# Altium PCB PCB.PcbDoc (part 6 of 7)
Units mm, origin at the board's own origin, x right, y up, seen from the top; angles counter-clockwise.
Board outline 243.2 x 142.8 mm, 4 copper layers (Top Layer, Layer 1, Layer 2, Bottom Layer), stack 0.603 mm thick; 451 components, 380 nets, 2276 pads, 1520 vias.
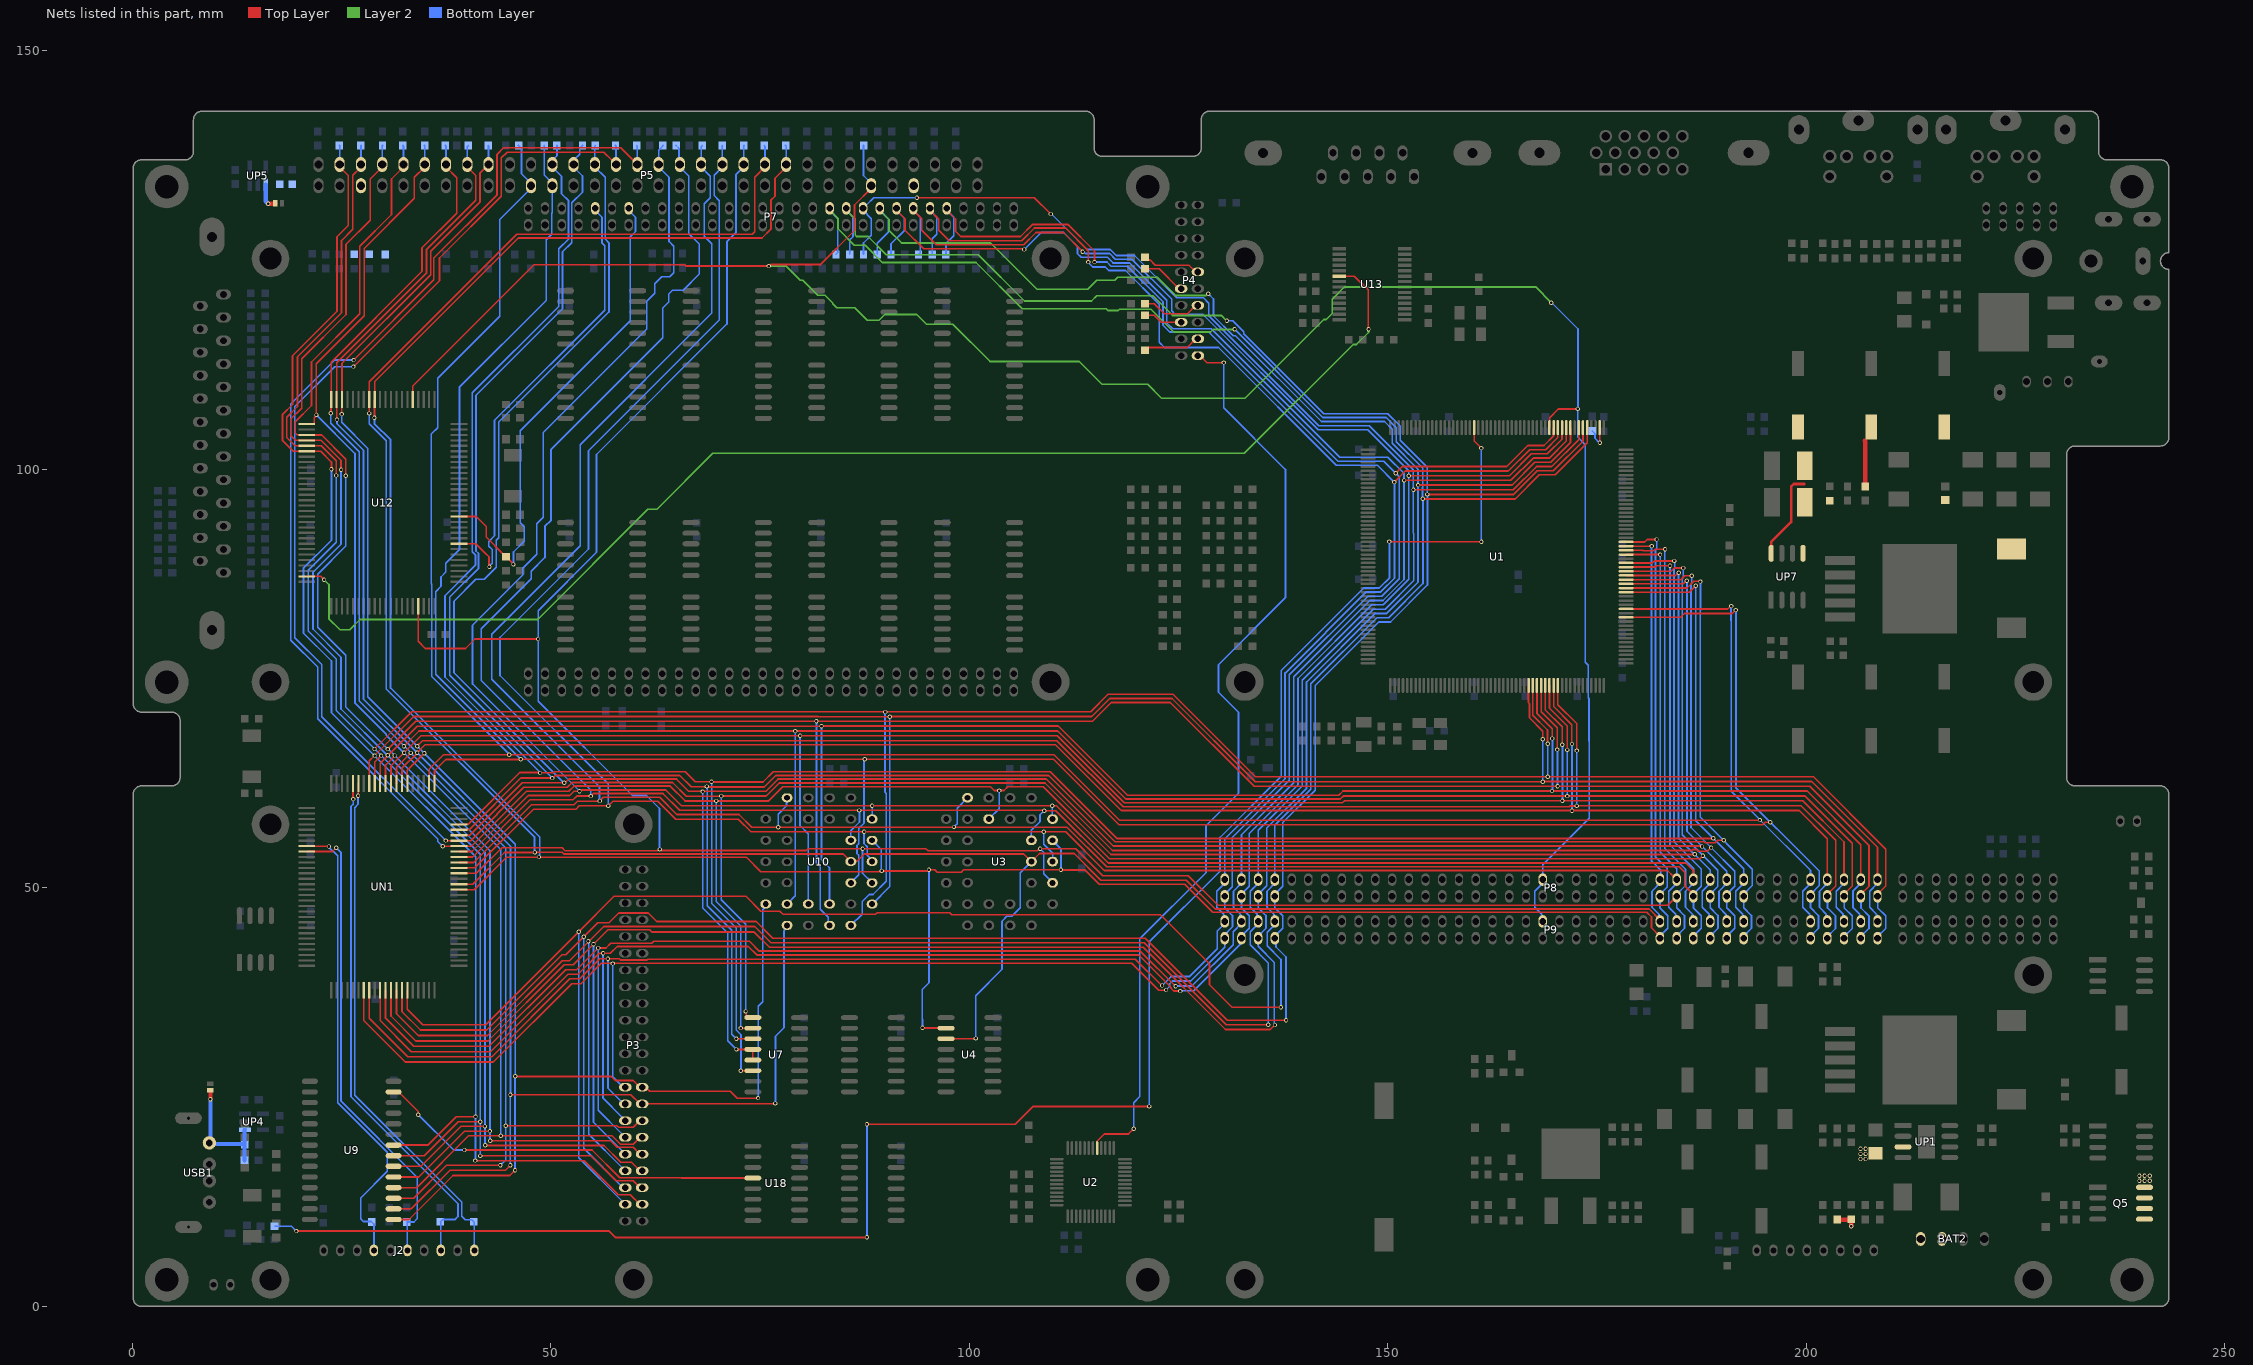
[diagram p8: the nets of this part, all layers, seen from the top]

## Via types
v1: diameter 0.508, hole 0.305, Top Layer to Bottom Layer, tented both sides, 1451 vias
v2: diameter 0.508, hole 0.3, Top Layer to Bottom Layer, 67 vias
v3: diameter 1.2, hole 1.2, Top Layer to Bottom Layer, 2 vias

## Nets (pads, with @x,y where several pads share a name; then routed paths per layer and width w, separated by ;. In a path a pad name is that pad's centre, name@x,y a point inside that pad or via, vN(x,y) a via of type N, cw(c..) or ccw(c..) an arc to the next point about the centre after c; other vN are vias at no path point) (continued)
SA8: P5.46 P8.28 P9.28 R71.1 U1.186 U3.27 U4.2 U10.27 U12.42 UN1.15 | length 364.3
  Top Layer w0.203: v1(28.916,106.188) 28.933,106.205 28.933,108.337 U12.42@28.951,108.354 28.951,110.506 46.095,127.651 75.221,127.651 76.287,128.717 76.287,132.146 76.77,132.629 76.77,134.8 78.11,136.14 P5.46@78.11,136.44 ; UN1.15@39.026,49.8 40.829,49.8 44.69,53.66 48.537,53.66 v1(48.576,53.7) ; v1@48.627,53.66 73.366,53.66 75.094,51.933 89.165,51.933 89.209,51.976 89.378,51.976 89.394,51.993 89.394,52.035 94.95,52.035 95.103,52.187 v1@95.185,52.187 ; v1(94.398,33.299) 94.422,33.275 97.187,33.275 U4.2@97.212,33.25 ; v1@95.236,52.187 95.865,52.187 96.157,51.895 99.008,51.895 99.3,52.187 v1(110.933,52.187) ; v1@110.933,52.136 113.827,52.136 115.511,50.452 125.724,50.452 129.094,47.082 180.935,47.082 181.494,46.523 181.494,45.256 182.5,44.25 P9.28@182.5,44 ; U1.186@178.463,91.336 180.692,91.336 180.99,91.633 v1(182.104,91.633)
  Bottom Layer w0.203: v1(28.916,106.188) 28.916,105.476 30.847,103.546 30.847,73.894 48.652,56.089 48.652,54.013 48.634,53.995 48.634,53.758 v1(48.576,53.7) ; R71.1@78.04,138.7 78.11,138.63 P5.46@78.11,136.44 ; U10.27@88.378,55.692 89.47,54.6 89.47,52.083 v1(89.518,52.035) ; v1(94.398,33.299) 94.398,34.287 94.372,34.313 94.372,37.862 95.17,38.659 95.17,52.177 v1(95.16,52.187) ; U3.27@109.942,55.692 110.933,54.702 v1(110.933,52.187) ; v1(182.104,91.633) 182.104,90.544 181.962,90.402 181.962,53.726 183.364,52.324 183.364,50.114 182.5,49.25 P8.28@182.5,49 182.5,47.638 183.437,46.701 183.437,45.187 182.5,44.25 P9.28@182.5,44
SA9: P5.44 P8.27 P9.27 R72.1 U1.185 U3.26 U4.3 U10.26 U12.43 UN1.16 | length 355.3
  Top Layer w0.203: v1(28.307,106.696) 28.304,106.699 28.304,108.351 U12.43@28.301,108.354 28.301,110.494 45.915,128.108 74.052,128.108 74.357,128.413 74.357,134.927 75.57,136.14 P5.44@75.57,136.44 ; UN1.16@39.026,50.45 40.667,50.45 44.461,54.245 v1(48.093,54.245) ; v1@48.093,54.259 51.344,54.259 51.551,54.051 84.939,54.051 U10.26@85.838,53.152 85.936,53.251 86.635,53.251 87.439,54.054 106.501,54.054 U3.26@107.402,53.152 108.368,54.118 112.532,54.118 115.712,50.937 125.924,50.937 129.373,47.488 181.215,47.488 182.5,46.203 P9.27@182.5,46 ; U4.3@97.212,31.98 97.232,32 100.728,32 v1(100.748,32.02) ; U1.185@178.463,90.836 178.468,90.841 181.514,90.841 v1(181.52,90.846)
  Bottom Layer w0.203: v1(28.307,106.696) 28.307,105.451 30.313,103.444 30.313,73.777 48.051,56.039 48.051,54.287 v1(48.093,54.245) ; R72.1@75.5,138.7 75.57,138.63 P5.44@75.57,136.44 ; v1(100.748,32.02) 100.748,37.125 103.897,40.275 103.897,46.04 104.481,46.625 105.066,46.625 106.082,47.641 106.082,51.832 U3.26@107.402,53.152 ; v1@181.491,90.897 181.491,90.846 181.491,53.232 182.612,52.111 182.612,51.112 P8.27@182.5,51 ; P9.27@182.384,46.116 182.384,46.865 181.558,47.691 181.558,49.622 P8.27@182.5,50.564
SA10: P5.42 P8.26 P9.26 R73.1 U1.184 U3.23 U10.23 U12.97 UN1.18 | length 333.7
  Top Layer w0.203: U12.97@34.151,83.654 34.151,79.46 34.997,78.614 39.798,78.614 40.931,79.746 v1(48.474,79.746) ; UN1.18@39.026,51.75 41.103,51.75 44.156,54.803 51.338,54.803 51.684,54.458 62.757,54.458 62.91,54.61 63.074,54.61 63.211,54.473 80.514,54.473 80.738,54.697 87.228,54.697 v1@87.23,54.7 ; v1(87.232,54.697) 94.803,54.697 95.065,54.435 108.12,54.435 108.361,54.676 v1(108.444,54.676) 108.469,54.702 112.71,54.702 115.935,51.476 126.148,51.476 129.704,47.92 183.42,47.92 184.098,48.598 184.132,48.598 184.5,48.966 P8.26@184.5,49 ; U1.184@178.463,90.336 180.48,90.336 180.528,90.287 181.751,90.287 181.929,90.465 v1(183.12,90.465)
  Bottom Layer w0.203: v1(62.992,54.61) 62.978,54.624 62.978,59.502 61.428,61.052 59.752,61.052 48.486,72.318 48.486,79.735 v1(48.474,79.746) 48.474,83.132 55.44,90.098 55.44,101.783 71.029,117.372 71.029,127.219 72.105,128.294 72.105,135.215 73.03,136.14 P5.42@73.03,136.44 73.03,138.668 R73.1@73.062,138.7 ; v1(87.232,54.697) 87.232,51.758 U10.23@88.378,50.612 ; v1(108.444,54.676) 108.876,54.245 108.876,51.679 U3.23@109.942,50.612 ; v1(183.12,90.465) 183.079,90.424 183.079,54.717 185.549,52.248 185.549,50.299 184.5,49.25 P8.26@184.5,49 184.5,47.638 185.437,46.701 185.437,45.187 P9.26@184.5,44.25
SA11: P5.40 P8.25 P9.25 R74.1 U1.183 U3.25 U10.25 UN1.19 | length 305.3
  Top Layer w0.203: UN1.19@39.026,52.4 40.915,52.4 47.916,59.401 52.996,59.401 53.404,59.809 56.854,59.809 v1(56.856,59.807) 57.415,60.366 62.748,60.366 64.897,58.217 72.391,58.217 73.9,56.708 v1(87.413,56.708) v1(108.876,56.708) 111.498,56.708 116.121,52.086 183.414,52.086 184.098,51.402 184.132,51.402 184.5,51.034 P8.25@184.5,51 ; U1.183@178.463,89.836 178.466,89.833 182.518,89.833 v1(182.52,89.83)
  Bottom Layer w0.203: v1(56.856,59.807) 56.856,62.449 43.928,75.377 43.928,79.923 54.494,90.49 54.494,102.222 70.128,117.856 70.128,132.108 69.506,132.731 69.506,135.156 70.49,136.14 P5.40@70.49,136.44 70.49,138.68 R74.1@70.471,138.7 ; v1(87.413,56.708) 87.413,55.307 87.791,54.929 87.791,53.916 88.378,53.329 U10.25@88.378,53.152 ; v1(108.876,56.708) 108.876,55.21 109.942,54.143 U3.25@109.942,53.152 ; v1(182.52,89.83) 182.55,89.801 182.55,54.256 184.5,52.306 P8.25@184.5,51 ; P9.25@184.384,46.116 184.384,46.865 183.558,47.691 183.558,49.622 P8.25@184.5,50.564
SA12: P5.38 P8.24 P9.24 R75.1 U1.181 U3.4 U10.4 UN1.20 | length 313.9
  Top Layer w0.203: UN1.20@39.026,53.05 40.777,53.05 47.685,59.958 52.765,59.958 53.173,60.366 55.815,60.366 v1(55.84,60.391) 56.272,60.823 63.002,60.823 65.043,58.782 72.473,58.782 73.988,57.267 v1(77.151,57.267) 98.157,57.267 111.668,57.267 116.401,52.534 184.805,52.534 185.482,51.857 185.482,50.268 186.5,49.25 P8.24@186.5,49 ; U1.181@178.463,88.836 181.577,88.836 181.81,89.068 v1(184.212,89.068)
  Bottom Layer w0.203: v1@55.8,60.391 55.8,62.083 42.94,74.943 42.94,80.333 53.506,90.899 53.506,102.964 69.226,118.684 69.226,126.965 68.337,127.854 68.337,131.74 69.048,132.451 69.048,135.042 67.95,136.14 P5.38@67.95,136.44 67.95,138.566 R75.1@68.083,138.7 ; v1(77.151,57.267) 77.151,58.817 78.152,59.818 78.152,60.707 U10.4@78.218,60.772 ; v1(98.157,57.293) 98.538,57.674 98.538,59.528 U3.4@99.782,60.772 ; v1(184.212,89.068) 184.263,89.017 184.263,88.209 184.187,88.133 184.187,55.515 187.438,52.263 187.438,50.188 186.5,49.25 P8.24@186.5,49 186.5,47.638 187.437,46.701 187.437,45.187 186.5,44.25 P9.24@186.5,44
SA13: P5.36 P8.23 P9.23 R76.1 U1.180 U3.28 U10.28 UN1.21 | length 308.7
  Top Layer w0.203: UN1.21@39.026,53.7 40.665,53.7 47.509,60.544 52.64,60.544 53.072,60.976 v1@54.775,60.976 ; v1(54.775,60.977) 55.078,61.28 63.383,61.28 65.389,59.274 86.839,59.274 v1(86.854,59.259) ; v1@86.854,59.274 108.9,59.274 v1(108.941,59.233) 110.338,59.233 116.587,52.983 185.601,52.983 186.5,52.084 P8.23@186.5,51 ; U1.180@178.463,88.336 181.875,88.336 182.049,88.509 v1(183.704,88.509)
  Bottom Layer w0.203: v1(54.775,60.977) 54.775,61.711 41.693,74.793 41.693,80.965 47.662,86.934 47.662,87.849 49.287,89.474 49.287,93.211 50.024,93.948 50.024,102.403 63.359,115.738 63.359,119.294 64.064,119.999 64.064,120.965 64.527,121.428 65.797,121.428 67.728,123.358 67.728,126.939 66.486,128.181 66.486,135.064 65.41,136.14 P5.36@65.41,136.44 65.297,136.553 65.297,138.357 R76.1@64.954,138.7 ; U10.28@85.838,55.692 85.838,56.835 86.879,57.877 86.879,59.233 v1(86.854,59.259) ; U3.28@107.402,55.692 107.402,56.882 108.444,57.924 108.444,58.763 108.914,59.233 v1(108.941,59.233) ; v1(183.704,88.509) 183.704,55.134 186.5,52.338 P8.23@186.5,51 ; P9.23@186.384,46.116 186.384,46.865 185.558,47.691 185.558,49.622 P8.23@186.5,50.564
SA14: P5.34 P8.22 P9.22 R77.1 U1.179 U3.29 U10.29 UN1.22 | length 306.6
  Top Layer w0.203: UN1.22@39.026,54.35 40.579,54.35 47.281,61.052 52.259,61.052 52.756,61.549 53.499,61.549 53.662,61.712 63.713,61.712 65.608,59.818 88.363,59.818 v1(88.378,59.833) ; v1@88.378,59.818 109.877,59.818 v1(109.892,59.833) ; v1@109.892,59.818 110.413,59.818 116.748,53.483 187.26,53.483 187.616,53.838 v1(187.641,53.838) ; U1.179@178.463,87.836 183.821,87.836 184.215,88.23 v1(185.279,88.23)
  Bottom Layer w0.203: v1(53.416,61.549) 53.416,61.59 40.626,74.38 40.626,81.372 46.646,87.392 46.646,88.204 48.297,89.855 48.297,93.513 49.079,94.295 49.079,104.407 51.415,106.744 51.421,106.744 61.454,116.777 61.454,120.081 62.406,121.034 62.406,122.177 63.257,123.028 64.198,123.028 64.68,123.51 64.68,126.685 64.121,127.244 64.121,134.889 62.87,136.14 P5.34@62.87,136.44 62.87,138.142 63.389,138.662 R77.1@63.389,138.7 ; U10.29@88.378,58.232 v1(88.378,59.833) ; v1(109.892,59.833) 109.917,59.807 109.917,58.258 U3.29@109.942,58.232 ; v1(185.279,88.23) 185.304,88.204 185.304,87.09 185.152,86.937 185.152,56.378 189.419,52.111 189.419,50.169 188.5,49.25 P8.22@188.5,49 188.5,47.638 189.437,46.701 189.437,45.187 188.5,44.25 P9.22@188.5,44
SA15: P5.32 P8.21 P9.21 R78.1 U1.178 U3.3 U7.2 UN1.23 | length 363.4
  Top Layer w0.203: v1(26.427,113.071) 36.011,122.655 36.011,125.266 43.572,132.828 43.572,137.658 44.334,138.42 58.35,138.42 59.839,136.931 59.87,136.931 60.33,136.47 P5.32@60.33,136.44 ; v1(37.07,54.981) 37.079,54.991 39.016,54.991 UN1.23@39.026,55 40.518,55 47.077,61.56 52.144,61.56 52.755,62.172 64.244,62.172 66.015,60.401 v1(69.76,60.401) 76.022,60.401 77.713,62.092 102.527,62.092 102.983,61.636 v1(103.567,61.636) 104.126,61.636 104.597,62.107 108.809,62.107 116.926,53.991 186.6,53.991 v1(186.65,54.041) ; v1(72.695,33.264) 72.702,33.257 74.121,33.257 U7.2@74.128,33.25 ; U1.178@178.463,87.336 184.353,87.336 184.663,87.646 v1(184.745,87.646)
  Bottom Layer w0.203: v1(26.427,113.071) 24.169,113.071 18.923,107.825 18.923,79.606 22.135,76.395 22.135,70.224 36.5,55.859 36.5,55.551 v1(37.07,54.981) ; R78.1@60.26,138.7 60.33,138.63 P5.32@60.33,136.44 ; v1(69.76,60.401) 69.76,48.377 72.681,45.456 72.681,33.278 v1(72.695,33.264) ; U3.3@102.322,58.232 103.567,59.477 v1(103.567,61.636) ; v1@184.72,87.646 184.72,55.921 186.6,54.041 v1(186.65,54.041) ; v1@186.625,54.016 188.5,52.141 P8.21@188.5,51 ; P9.21@188.5,46 188.384,46.116 188.384,46.865 187.558,47.691 187.558,49.622 P8.21@188.5,50.564
SA16: P5.30 P8.20 P9.20 R79.1 U1.177 U7.1 UN1.24 | length 359.6
  Top Layer w0.203: v1(26.413,112.298) 26.444,112.298 36.687,122.541 36.687,125.257 44.08,132.65 44.08,137.226 44.766,137.912 56.318,137.912 57.299,136.931 57.33,136.931 57.79,136.47 P5.30@57.79,136.44 ; v1(37.451,55.667) 37.459,55.659 39.017,55.659 UN1.24@39.026,55.65 40.406,55.65 46.773,62.017 51.954,62.017 52.533,62.596 64.531,62.596 66.167,60.96 70.333,60.96 v1(70.358,60.985) 75.738,60.985 77.291,62.538 109.025,62.538 117.09,54.473 186.292,54.473 186.419,54.6 186.882,54.6 187.085,54.397 188.174,54.397 v1(188.606,54.829) ; v1(73.265,35.245) 73.265,35.163 73.324,35.104 73.324,34.684 73.488,34.52 U7.1@74.128,34.52 ; U1.177@178.463,86.836 185.002,86.836 185.457,87.29 v1(186.295,87.29)
  Bottom Layer w0.203: v1(26.413,112.298) 26.399,112.284 24.167,112.284 19.406,107.523 19.406,79.908 22.617,76.697 22.617,70.475 37.425,55.667 v1(37.451,55.667) ; R79.1@57.72,138.7 57.79,138.63 P5.30@57.79,136.44 ; v1(70.358,60.985) 70.344,60.971 70.344,48.606 73.265,45.685 v1(73.265,35.245) ; v1(186.295,87.29) 186.295,86.404 186.219,86.328 186.219,57.216 v1(188.606,54.829) 191.451,51.984 191.451,50.201 190.5,49.25 P8.20@190.5,49 190.5,47.638 191.437,46.701 191.437,45.187 190.5,44.25 P9.20@190.5,44
SA17: P5.28 P8.19 P9.19 R80.1 U1.176 U7.4 U7.5 UN1.25 | length 332.4
  Top Layer w0.203: UN1.25@39.026,56.3 40.294,56.3 46.569,62.576 v1(51.599,62.576) 51.681,62.576 52.126,63.021 64.995,63.021 66.446,61.57 68.067,61.57 v1(68.118,61.519) ; v1@68.118,61.57 75.692,61.57 77.143,63.021 109.177,63.021 117.192,55.007 187.489,55.007 v1(187.539,54.956) ; v1(72.161,30.71) U7.4@74.128,30.71 U7.5@74.128,29.44 ; U1.176@178.463,86.336 185.29,86.336 185.66,86.706 v1(185.711,86.706)
  Bottom Layer w0.203: v1@51.548,62.576 38.416,75.708 38.416,84.267 41.032,86.884 42.023,86.884 43.471,88.331 43.471,91.532 43.78,91.842 43.78,105.663 56.933,118.815 56.933,127.092 56.486,127.539 56.486,134.904 55.25,136.14 P5.28@55.25,136.44 55.25,138.643 R80.1@55.307,138.7 ; v1(68.118,61.519) 68.148,61.489 68.148,47.6 71.12,44.628 71.12,31.751 v1(72.161,30.71) ; v1(185.711,86.706) 185.736,86.68 185.736,56.759 v1(187.539,54.956) 190.5,51.995 P8.19@190.5,51 ; P9.19@190.384,46.116 190.384,46.865 189.558,47.691 189.558,49.622 P8.19@190.5,50.564
SA18: P5.26 P8.18 P9.18 R81.1 U1.175 U7.3 UN1.26 | length 335.8
  Top Layer w0.203: UN1.26@39.026,56.95 40.232,56.95 46.417,63.135 50.204,63.135 50.515,63.445 65.409,63.445 66.777,62.078 68.568,62.078 v1(68.619,62.128) ; v1@68.605,62.052 75.467,62.052 76.86,63.445 109.464,63.445 117.395,55.515 187.771,55.515 187.898,55.388 189.117,55.388 189.422,55.692 v1(190.13,55.692) ; v1(72.161,31.98) U7.3@74.128,31.98 ; U1.175@178.463,85.836 185.727,85.836 186.546,86.655 187.285,86.655 v1(187.336,86.604)
  Bottom Layer w0.203: v1(50.176,63.135) 37.908,75.403 37.908,84.756 41.362,88.21 41.362,89.954 41.058,90.259 41.058,108.88 51.395,119.218 51.395,126 52.495,127.099 52.495,131.849 53.783,133.137 53.783,135.067 52.71,136.14 P5.26@52.71,136.44 52.71,136.941 53.436,137.667 53.436,138.357 R81.1@53.779,138.7 ; v1(68.619,62.128) 68.677,62.07 68.677,47.858 71.603,44.933 71.603,32.539 v1(72.161,31.98) ; v1@187.336,86.583 187.336,83.192 187.311,83.167 187.311,72.466 187.315,72.462 187.315,58.481 193.549,52.248 193.549,50.299 192.5,49.25 P8.18@192.5,49 192.5,47.638 193.437,46.701 193.437,45.187 P9.18@192.5,44.25
SA19: P5.24 P8.17 P9.17 R82.1 U1.174 U7.6 UN1.27 | length 332.6
  Top Layer w0.203: UN1.27@39.026,57.6 39.054,57.628 40.123,57.628 46.29,63.795 48.432,63.795 ; 48.432,63.794 48.645,63.794 v1(48.703,63.736) ; v1@48.703,63.77 50.301,63.77 50.401,63.87 66.051,63.87 67.234,62.687 v1(69.19,62.687) 69.215,62.662 75.347,62.662 76.556,63.87 109.663,63.87 117.612,55.921 188.86,55.921 v1(188.886,55.946) ; v1@72.696,28.169 U7.6@74.128,28.169 ; U1.174@178.463,85.336 186.017,85.336 v1(186.777,86.096)
  Bottom Layer w0.203: v1(48.703,63.736) 48.703,63.818 48.566,63.955 48.566,63.983 37.349,75.2 37.349,84.928 40.981,88.56 40.981,89.796 40.62,90.157 40.62,109.154 50.938,119.472 50.938,126.355 52.114,127.531 52.114,132.088 51.268,132.934 51.268,135.042 50.17,136.14 P5.24@50.17,136.44 50.17,136.911 50.724,137.465 R82.1@50.724,138.7 ; v1(69.19,62.687) 69.201,62.676 69.201,48.147 72.136,45.212 72.136,33.033 72.72,32.449 72.72,28.194 v1(72.695,28.169) ; v1(186.777,86.096) 186.777,75.779 186.786,75.77 186.786,58.02 192.5,52.306 P8.17@192.5,51 ; P9.17@192.384,46.116 192.384,46.865 191.558,47.691 191.558,49.622 P8.17@192.5,50.564
SD0: P3.17 P5.18 P8.8 P9.8 R45.1 U1.145 U9.15 U10.13 U12.48 UN1.36 | length 416.1
  Top Layer w0.203: v1(25.005,106.619) 25.028,106.642 25.028,108.331 U12.48@25.051,108.354 25.051,112.669 35.63,123.248 35.63,126.058 41.54,131.969 41.54,135.43 P5.18@42.55,136.44 ; U9.15@31.2,10.39 33.042,10.39 38.299,15.646 45.085,15.646 v1(45.72,16.281) ; UN1.36@32.851,62.475 32.851,64.046 v1(34.885,66.081) ; v1(34.026,66.946) 34.026,66.974 34.657,67.605 110.449,67.605 118.364,59.69 171.671,59.69 171.763,59.782 172.528,59.782 172.579,59.833 199.35,59.833 203.491,55.692 203.491,50.241 202.5,49.25 P8.8@202.5,49 ; v1@45.779,27.483 57.201,27.483 57.679,27.005 59.845,27.005 60.65,26.2 P3.17@60.9,26.2 61.31,26.2 61.799,25.711 71.444,25.711 72.262,24.893 v1(74.752,24.893) ; U1.145@170.305,74.206 170.305,71.89 172.553,69.641 v1(172.553,66.411)
  Bottom Layer w0.203: v1(25.005,106.619) 25.005,105.629 28.129,102.505 28.129,72.831 v1@34.014,66.946 ; v1(34.026,66.946) v1@34.014,66.946 ; R45.1@42.531,138.7 42.55,138.68 P5.18@42.55,136.44 ; v1(45.72,16.281) v1@45.72,27.497 ; v1(45.731,27.508) 45.731,55.229 v1@34.014,66.946 ; v1@74.778,24.867 74.778,35.871 75.311,36.404 75.311,47.409 75.678,47.776 U10.13@75.678,48.072 ; v1(172.553,59.807) v1(172.553,66.411) ; P9.8@202.532,44.212 203.469,45.15 203.469,46.663 202.532,47.601 P8.8@202.532,48.962
SD1: P3.15 P5.16 P8.7 P9.7 R46.1 U1.144 U9.16 U10.14 U12.49 UN1.37 | length 411.8
  Top Layer w0.203: v1(24.446,105.959) 24.423,105.982 24.423,108.331 U12.49@24.401,108.354 24.401,112.73 35.127,123.456 35.127,126.266 41.032,132.172 41.032,135.118 40.01,136.14 P5.16@40.01,136.44 ; U9.16@31.2,11.66 33.322,11.66 37.943,16.281 44.576,16.281 v1(45.161,16.867) ; UN1.37@32.201,62.475 32.201,64.282 34.017,66.099 v1(34.017,66.153) 34.023,66.153 34.967,67.097 110.297,67.097 118.145,59.248 171.969,59.248 v1(171.995,59.223) ; v1(45.161,25.298) 59.552,25.298 60.65,24.2 P3.15@60.9,24.2 60.929,24.229 76.781,24.229 v1(76.81,24.257) ; U1.144@169.805,74.206 169.805,71.683 171.969,69.518 171.969,67.224 v1(171.995,67.199) ; v1@171.995,59.248 199.147,59.248 202.5,55.896 P8.7@202.5,51
  Bottom Layer w0.203: v1(24.446,105.959) 24.446,105.451 27.615,102.282 27.615,72.567 34.017,66.165 v1(34.017,66.153) 45.172,54.998 45.172,25.31 v1(45.161,25.298) v1(45.161,16.867) ; P5.16@40.01,136.44 40.01,138.566 R46.1@40.143,138.7 ; v1(76.81,24.257) 76.835,24.282 76.835,32.283 77.851,33.299 77.851,44.869 78.218,45.236 U10.14@78.218,45.532 ; v1(171.995,59.223) v1(171.995,67.199) ; P9.7@202.384,46.116 202.384,46.865 201.558,47.691 201.558,49.622 P8.7@202.5,50.564
SD2: P3.13 P5.14 P8.6 P9.6 R47.1 U1.143 U9.17 U10.15 U12.50 UN1.38 | length 400.1
  Top Layer w0.203: v1(23.709,106.721) 23.73,106.742 23.73,108.333 U12.50@23.751,108.354 23.751,112.817 34.606,123.672 34.606,126.482 38.746,130.622 38.746,134.864 37.47,136.14 P5.14@37.47,136.44 ; U9.17@31.2,12.93 33.601,12.93 37.537,16.866 v1(43.967,16.866) ; UN1.38@31.551,62.475 31.551,64.423 v1(33.26,66.132) ; v1(32.446,66.946) 34.248,68.748 v1(79.208,68.748) 110.551,68.748 118.669,60.63 144.316,60.63 144.662,60.976 v1(171.436,60.976) 199.858,60.976 205.491,55.343 205.491,50.241 204.5,49.25 P8.6@204.5,49 ; v1(44.602,21.59) 57.887,21.59 58.081,21.395 59.845,21.395 60.65,22.2 P3.13@60.9,22.2 ; U1.143@169.305,74.206 169.305,71.476 171.436,69.344 v1(171.436,66.487)
  Bottom Layer w0.203: v1(23.709,106.721) 23.709,105.527 27.1,102.136 27.1,72.342 v1@33.254,66.189 ; v1@33.254,66.126 44.602,54.777 v1(44.602,21.59) 44.602,17.501 v1(43.967,16.866) ; R47.1@37.4,138.7 37.47,138.63 P5.14@37.47,136.44 ; U10.15@78.218,48.072 79.208,49.063 v1(79.208,68.748) ; v1(171.436,60.976) v1(171.436,66.487) ; P9.6@204.532,44.212 205.469,45.15 205.469,46.663 204.532,47.601 P8.6@204.532,48.962
SD3: P3.11 P5.12 P8.5 P9.5 R48.1 U1.142 U9.18 U10.17 U12.51 UN1.39 | length 395.6
  Top Layer w0.203: U12.51@20.826,105.429 21.696,105.429 21.724,105.457 21.724,106.177 21.982,106.435 v1(21.982,106.518) 21.957,106.543 21.957,112.611 27.697,118.351 27.697,126.406 33.692,132.4 33.692,134.902 34.93,136.14 P5.12@34.93,136.44 ; UN1.39@30.901,62.475 30.901,64.611 v1@32.451,66.161 ; U9.18@31.2,14.2 33.957,14.2 40.153,20.396 v1(44.018,20.396) 57.302,20.396 58.313,19.386 59.836,19.386 60.65,20.2 P3.11@60.9,20.2 ; v1@32.454,66.164 34.479,68.189 v1(79.767,68.189) 110.5,68.189 118.516,60.173 144.584,60.173 144.828,60.417 v1(170.852,60.417) 199.579,60.417 204.5,55.496 P8.5@204.5,51 ; U1.142@168.805,74.206 168.805,71.269 170.826,69.247 v1(170.826,67.097)
  Bottom Layer w0.203: v1(21.982,106.518) 26.586,101.914 26.586,72.123 30.339,68.37 30.339,68.263 32.441,66.161 v1(32.458,66.161) ; v1@32.446,66.156 44.004,54.597 44.004,33.391 44.017,33.379 44.017,20.398 v1(44.018,20.396) ; R48.1@34.911,138.7 34.93,138.68 P5.12@34.93,136.44 ; v1(79.767,68.189) 79.767,57.47 80.758,56.48 U10.17@80.758,48.072 ; v1(170.826,67.097) 170.852,67.072 v1(170.852,60.417) ; P9.5@204.5,46 204.384,46.116 204.384,46.865 203.558,47.691 203.558,49.622 P8.5@204.5,50.564
SD4: P3.9 P5.10 P8.4 P9.4 R49.1 U1.141 U9.19 U10.18 U12.53 UN1.40 | length 411.2
  Top Layer w0.203: v1(25.487,99.253) 25.487,101.235 22.593,104.129 U12.53@20.826,104.129 20.799,104.156 19.671,104.156 19.468,104.359 19.468,105.705 21.398,107.635 21.398,112.842 27.164,118.608 27.164,126.685 30.948,130.47 30.948,134.698 32.39,136.14 P5.10@32.39,136.44 ; UN1.40@30.251,62.475 30.251,64.697 31.328,65.775 v1(31.328,65.828) ; v1(30.512,66.593) 33.835,69.916 90.241,69.916 90.255,69.903 114.709,69.903 116.967,72.161 124.003,72.161 134.02,62.144 v1(170.274,62.144) 200.404,62.144 207.491,55.057 207.491,50.241 206.5,49.25 P8.4@206.5,49 ; U9.19@31.2,15.47 34.211,15.47 39.67,20.93 42.697,20.93 v1(42.722,20.955) ; v1(42.748,19.787) 42.774,19.812 57.125,19.812 57.932,19.005 59.845,19.005 60.65,18.2 P3.9@60.9,18.2 ; U1.141@168.305,74.206 168.305,71.061 170.242,69.124 v1(170.242,66.538)
  Bottom Layer w0.203: v1(25.487,99.253) 25.487,92.218 25.487,90.849 22.135,87.497 22.135,81.165 25.487,77.812 25.487,71.618 30.484,66.621 30.54,66.621 30.54,66.616 30.545,66.616 31.328,65.834 v1(31.328,65.828) ; v1@31.331,65.831 42.722,54.44 v1(42.722,20.955) 42.735,20.942 42.735,19.8 v1(42.748,19.787) ; R49.1@32.32,138.7 32.39,138.63 P5.10@32.39,136.44 ; v1(81.723,69.916) 81.723,52.975 82.18,52.517 82.18,47.437 83.13,46.487 83.13,45.7 U10.18@83.298,45.532 U10.18@83.323,45.507 ; v1(170.242,66.538) 170.258,66.522 170.258,62.16 v1(170.274,62.144) ; P9.4@206.532,44.212 207.469,45.15 207.469,46.663 206.532,47.601 P8.4@206.532,48.962
SD5: P3.7 P5.8 P8.3 P9.3 R50.1 U1.140 U9.20 U10.19 U12.54 UN1.41 | length 403
  Top Layer w0.203: v1(24.929,99.965) 24.929,101.082 22.532,103.479 U12.54@20.826,103.479 19.484,103.479 18.934,104.029 18.934,106.022 20.23,107.318 20.23,113.225 25.513,118.509 25.513,126.889 28.408,129.784 28.408,134.698 29.85,136.14 P5.8@29.85,136.44 ; UN1.41@29.601,62.475 29.601,64.908 30.505,65.813 v1@30.505,65.864 ; v1(30.505,65.866) v1@30.505,65.864 ; U9.20@31.2,16.74 34.49,16.74 39.264,21.514 v1(42.113,21.514) ; v1(42.151,19.253) 42.176,19.228 56.337,19.228 58.344,17.221 59.629,17.221 60.65,16.2 P3.7@60.9,16.2 ; v1(82.333,69.332) 34.041,69.332 31.887,67.177 30.573,65.864 v1@30.505,65.864 ; v1@82.333,69.358 110.601,69.358 118.897,61.062 144.12,61.062 144.643,61.585 v1(169.607,61.585) 200.087,61.585 206.5,55.172 P8.3@206.5,51 ; U1.140@167.805,74.206 167.805,70.854 169.632,69.027 v1(169.632,67.859)
  Bottom Layer w0.203: v1(24.929,99.965) 24.929,91.081 21.576,87.728 21.576,80.934 24.929,77.581 24.929,71.387 v1@30.449,65.866 ; P5.8@29.85,136.44 29.85,138.668 R50.1@29.882,138.7 ; v1@30.502,65.864 42.126,54.24 42.126,19.278 v1(42.151,19.253) ; v1(82.333,69.332) 82.333,53.356 83.298,52.39 U10.19@83.298,48.072 ; v1(169.607,61.585) 169.658,61.636 169.658,67.834 v1(169.632,67.859) ; P9.3@206.384,46.116 206.384,46.865 205.558,47.691 205.558,49.622 P8.3@206.5,50.564
SD6: P3.5 P5.6 P8.2 P9.2 R51.1 U1.139 U9.21 U10.20 U12.55 UN1.42 | length 416.9
  Top Layer w0.203: v1(24.37,99.279) 24.37,101.031 22.572,102.829 U12.55@20.826,102.829 19.423,102.829 18.426,103.825 18.426,106.233 19.722,107.528 19.722,113.472 24.979,118.729 24.979,127.346 26.326,128.692 26.326,135.156 27.31,136.14 P5.6@27.31,136.44 ; v1(28.923,66.602) 33.371,71.05 v1@89.924,71.05 ; UN1.42@28.951,62.475 28.951,65.048 v1(29.714,65.811) ; U9.21@31.2,18.01 34.871,18.01 38.934,22.073 v1(41.554,22.073) ; v1@41.556,18.009 54.788,18.009 57.792,15.005 59.845,15.005 60.65,14.2 P3.5@60.9,14.2 ; v1@89.953,71.05 114.484,71.05 116.561,73.127 124.333,73.127 134.182,63.277 169.089,63.277 v1(169.099,63.287) 200.846,63.287 209.491,54.643 209.491,50.241 208.5,49.25 P8.2@208.5,49 ; U1.139@167.305,74.206 167.305,70.647 169.074,68.878 169.074,67.249 v1(169.099,67.224)
  Bottom Layer w0.203: v1(24.37,99.279) 24.37,92.218 24.37,91.312 21.017,87.96 21.017,80.702 24.37,77.349 24.37,71.211 41.554,54.027 v1(41.554,22.073) 41.554,17.986 v1(41.556,17.985) ; R51.1@27.308,138.7 27.31,138.697 P5.6@27.31,136.44 ; U10.20@85.838,45.532 87.184,46.879 87.184,48.377 88.03,49.223 88.487,49.223 90.077,50.813 90.077,61.273 89.927,61.423 89.927,70.995 v1(89.953,71.021) ; v1(169.099,63.287) v1(169.099,67.224) ; P9.2@208.532,44.212 209.469,45.15 209.469,46.663 208.532,47.601 P8.2@208.532,48.962
SD7: P3.3 P5.4 P8.1 P9.1 R52.1 U1.138 U9.22 U10.21 U12.56 UN1.43 | length 410.4
  Top Layer w0.203: v1(23.786,100.015) 23.786,100.882 22.489,102.179 U12.56@20.826,102.179 19.209,102.179 17.944,103.444 17.944,106.576 19.137,107.77 19.137,113.579 24.446,118.888 24.446,127.803 25.792,129.149 25.792,135.118 24.77,136.14 P5.4@24.77,136.44 ; UN1.43@28.301,62.475 28.301,65.189 v1(28.933,65.821) 33.587,70.475 81.954,70.475 81.968,70.462 v1(90.486,70.462) ; U9.22@31.2,19.28 35.278,19.28 38.68,22.682 v1(40.996,22.682) ; v1(40.97,17.424) 40.972,17.426 53.974,17.426 58.039,13.36 59.49,13.36 60.65,12.2 P3.3@60.9,12.2 ; v1@90.486,70.475 114.595,70.475 116.764,72.644 124.206,72.644 134.147,62.703 v1(168.515,62.703) 168.54,62.728 200.646,62.728 208.5,54.874 P8.1@208.5,51 ; U1.138@166.805,74.206 166.805,72.12 166.922,72.002 166.922,70.323 168.515,68.73 v1(168.515,67.757)
  Bottom Layer w0.203: v1(23.786,100.015) 23.786,92.218 23.786,91.554 20.433,88.202 20.433,80.46 23.786,77.107 23.786,70.949 v1@28.913,65.821 ; R52.1@24.734,138.7 24.77,138.663 P5.4@24.77,136.44 ; v1@28.923,65.811 41.007,53.728 41.007,22.693 v1(40.996,22.682) 40.983,22.669 40.983,17.437 v1(40.97,17.424) ; U10.21@88.378,48.072 90.486,50.181 v1(90.486,70.462) ; v1(168.515,62.703) v1(168.515,67.757) ; P9.1@208.384,46.116 208.384,46.865 207.558,47.691 207.558,49.622 P8.1@208.5,50.564
SD8: P3.4 P7.38 P8.73 P9.73 R53.1 U1.5 UN1.95 | length 345.9
  Top Layer w0.203: UN1.95@32.851,37.775 32.851,35.503 34.682,33.672 42.237,33.672 v1@53.33,44.765 ; v1(53.315,44.78) 57.539,49.005 73.312,49.005 75.082,47.234 77.353,47.234 77.734,46.853 88.788,46.853 88.991,47.056 97.643,47.056 97.885,46.815 122.833,46.815 128.688,40.96 128.688,38.446 131.38,35.753 v1(137.222,35.753) ; v1(154.164,96.493) 154.198,96.459 165.185,96.459 168.08,99.355 169.98,99.355 173.805,103.18 U1.5@173.805,104.994
  Layer 2 w0.203: P7.38@83.3,131.2 83.3,130.95 84.314,129.936 84.314,128.725 86.264,126.775 87.551,126.775 89.607,124.719 100.782,124.719 106.301,119.2 116.335,119.2 116.546,118.989 117.791,118.989 117.943,119.142 121.703,119.142 124.43,116.414 128.805,116.414 129.119,116.729 131.657,116.729 v1(131.683,116.755)
  Bottom Layer w0.203: v1(53.315,44.78) 53.34,44.755 53.34,17.76 58.498,12.602 58.498,12.568 58.866,12.2 P3.4@58.9,12.2 ; P7.38@83.3,131.2 83.3,130.95 84.288,129.962 84.288,125.922 R53.1@84.067,125.7 ; v1(131.683,116.755) 142.223,106.215 149.793,106.215 151.01,104.998 151.01,103.321 154.164,100.168 154.164,97.904 154.138,97.879 154.138,96.519 v1(154.164,96.493) 154.189,96.468 154.189,86.386 150.092,82.289 148.695,82.289 140.801,74.394 140.801,61.811 136.5,57.51 P8.73@136.5,51 ; P9.73@136.384,46.116 136.384,46.865 135.558,47.691 135.558,49.622 P8.73@136.5,50.564 ; P9.73@136.5,46 136.5,45.623 135.571,44.694 135.571,43.094 137.222,41.443 v1(137.222,35.753)
SD9: P3.6 P7.40 P8.74 P9.74 R54.1 U1.6 UN1.94 | length 342.1
  Top Layer w0.203: UN1.94@32.201,37.775 32.201,35.234 34.413,33.022 42.318,33.022 51.333,42.037 51.765,42.037 55.588,45.86 56.937,45.86 58.091,47.014 61.647,47.014 62.662,45.999 74.521,45.999 76.512,44.008 121.017,44.008 130.821,34.204 v1(137.83,34.204) ; v1(154.697,97.018) 165.035,97.018 167.864,99.847 169.765,99.847 173.305,103.387 173.305,103.804 U1.6@173.305,104.994
  Layer 2 w0.203: P7.40@85.3,131.2 85.3,130.95 86.346,129.904 86.346,128.006 86.524,127.828 87.895,127.828 90.072,125.651 101.071,125.651 106.59,120.132 114.591,120.132 115.199,120.74 121.933,120.74 124.268,118.405 130.085,118.405 130.72,117.77 v1(130.77,117.77)
  Bottom Layer w0.203: v1(53.922,44.171) 53.922,18.9 58.622,14.2 P3.6@58.9,14.2 ; P7.40@85.3,131.2 85.3,130.95 86.105,130.145 86.105,127.841 85.708,127.445 R54.1@85.708,125.7 ; v1(130.77,117.77) 131.459,117.77 132.769,116.46 132.769,116.215 142.319,106.664 149.979,106.664 151.459,105.184 151.459,103.507 154.697,100.269 v1(154.697,97.018) 154.723,96.993 154.723,86.193 150.305,81.775 148.908,81.775 141.314,74.181 141.314,61.69 137.451,57.826 137.451,50.201 136.5,49.25 P8.74@136.5,49 136.5,47.638 137.437,46.701 137.437,45.187 136.5,44.25 P9.74@136.5,44 136.634,43.866 136.634,42.945 137.82,41.759 137.82,34.214 v1(137.83,34.204)
SD10: P3.8 P7.42 P8.75 P9.75 R55.1 U1.7 UN1.93 | length 334.5
  Top Layer w0.203: UN1.93@31.551,37.775 31.551,34.965 34.144,32.372 42.43,32.372 51.359,41.3 52.222,41.3 56.317,45.395 74.356,45.395 76.302,43.45 120.89,43.45 130.694,33.645 v1(135.698,33.645) ; v1(93.737,132.477) 107.758,132.477 v1(109.714,130.521) ; v1(153.046,97.577) 164.992,97.577 167.766,100.351 169.587,100.351 172.805,103.569 U1.7@172.805,104.994
  Bottom Layer w0.203: v1(54.48,43.643) 54.534,43.59 54.534,20.566 58.498,16.602 58.498,16.568 58.866,16.2 P3.8@58.9,16.2 ; R55.1@87.35,125.7 87.35,127.055 88.276,127.981 88.276,129.974 87.3,130.95 P7.42@87.3,131.2 87.3,131.234 87.668,131.602 87.702,131.602 88.577,132.477 v1(93.737,132.477) ; v1(109.714,130.521) 109.818,130.521 114.06,126.279 116.826,126.279 117.537,125.568 119.721,125.568 124.776,120.513 127.976,120.513 128.611,119.878 128.611,118.346 141.735,105.222 147.788,105.222 153.046,99.965 v1(153.046,97.577) 153.046,92.4 153.091,92.355 153.091,86.741 149.667,83.316 148.27,83.316 139.773,74.82 139.773,62.181 134.5,56.907 P8.75@134.5,51 ; P9.75@134.384,46.116 134.384,46.865 133.558,47.691 133.558,49.622 P8.75@134.5,50.564 ; P9.75@134.5,46 134.5,45.711 133.539,44.75 133.539,43.196 135.698,41.037 v1(135.698,33.645)
SD11: P3.10 P7.44 P8.76 P9.76 R56.1 U1.9 UN1.92 | length 334.2
  Top Layer w0.203: UN1.92@30.901,37.775 30.901,34.696 33.874,31.722 42.491,31.722 51.613,40.843 52.654,40.843 v1(55.093,43.282) 56.825,45.014 61.793,45.014 62.078,44.729 74.311,44.729 76.124,42.916 120.769,42.916 130.598,33.086 135.956,33.086 v1(136.5,33.63) ; v1(153.605,98.136) 164.838,98.136 167.557,100.855 169.465,100.855 171.805,103.195 U1.9@171.805,104.994
  Layer 2 w0.203: P7.44@89.3,131.2 89.3,130.95 90.384,129.866 90.384,128.565 91.9,127.049 102.567,127.049 108.079,121.537 114.141,121.537 115.226,122.621 117.385,122.621 117.715,122.952 122.465,122.952 124.621,120.795 128.264,120.795 128.464,120.996 v1(128.535,120.996)
  Bottom Layer w0.203: v1(55.093,43.282) 55.093,22.007 58.498,18.602 58.498,18.568 58.866,18.2 P3.10@58.9,18.2 ; R56.1@88.992,125.7 88.992,127.02 90.308,128.336 90.308,129.942 89.3,130.95 P7.44@89.3,131.2 ; v1(128.535,120.996) 129.17,120.361 129.17,118.326 131.504,115.992 131.801,115.992 142.062,105.73 149.592,105.73 150.525,104.797 150.525,103.12 153.605,100.041 v1(153.605,98.136) 153.605,86.528 149.88,82.803 148.483,82.803 140.287,74.607 140.287,61.932 135.52,57.166 135.52,50.27 134.5,49.25 P8.76@134.5,49 134.5,47.638 135.437,46.701 135.437,45.187 134.5,44.25 P9.76@134.5,44 134.5,43.022 136.435,41.087 v1@136.435,33.63
SD12: P3.12 P7.46 P8.77 P9.77 R57.1 U1.10 UN1.91 | length 313.8
  Top Layer w0.203: UN1.91@30.251,37.775 30.251,34.426 33.605,31.072 42.603,31.072 51.765,40.234 53.061,40.234 v1(55.651,42.824) 56.591,42.824 57.153,43.386 62.055,43.386 62.306,43.637 73.736,43.637 74.914,42.459 120.43,42.459 124.632,38.257 v1(124.638,38.257) ; P7.46@91.3,131.2 91.3,130.95 92.315,129.935 92.315,128.59 94.55,126.355 v1@106.564,126.355 ; v1(151.929,98.695) 164.684,98.695 167.348,101.359 169.262,101.359 171.305,103.402 U1.10@171.305,104.994
  Bottom Layer w0.203: v1(55.651,42.824) 55.651,23.449 58.498,20.602 58.498,20.568 58.866,20.2 P3.12@58.9,20.2 ; R57.1@90.633,125.7 90.633,126.96 92.213,128.54 92.213,130.037 91.3,130.95 P7.46@91.3,131.2 ; v1(106.564,126.279) 108.596,128.311 111.238,128.311 112.914,126.635 112.914,125.771 113.346,125.339 116.496,125.339 117.169,124.666 119.15,124.666 123.582,120.234 123.582,117.491 124.278,116.795 128.9,116.795 144.232,101.463 149.998,101.463 151.929,99.533 v1(151.929,98.695) 151.929,86.858 149.414,84.344 147.844,84.344 138.746,75.245 138.746,62.576 132.5,56.33 P8.77@132.5,51 132.5,50.564 131.558,49.622 131.558,47.691 132.384,46.865 132.384,46.116 P9.77@132.5,46 132.5,45.75 131.507,44.757 131.507,43.221 126.579,38.293 124.674,38.293 v1(124.638,38.257)
SD13: P3.14 P7.48 P8.78 P9.78 R58.1 U1.11 UN1.90 | length 307.9
  Top Layer w0.203: UN1.90@29.601,37.775 29.601,34.157 33.336,30.422 42.792,30.422 52.045,39.675 53.238,39.675 55.766,42.202 57.112,42.202 57.915,43.005 73.581,43.005 74.584,42.002 120.207,42.002 124.09,38.118 124.09,38.014 124.422,37.682 v1(125.206,37.682) ; P7.48@93.3,131.2 93.3,130.95 94.296,129.954 94.296,128.565 96.023,126.838 106.488,126.838 107.961,128.311 111.238,128.311 v1(113.524,126.025) ; v1(152.487,99.253) 164.53,99.253 167.14,101.863 169.059,101.863 170.805,103.609 U1.11@170.805,104.994
  Bottom Layer w0.203: v1(56.236,42.189) 56.236,24.864 58.498,22.602 58.498,22.568 58.866,22.2 P3.14@58.9,22.2 ; P7.48@93.3,131.2 93.3,130.95 94.114,130.136 94.114,125.898 R58.1@93.917,125.7 ; v1(113.524,126.025) 113.606,126.025 113.835,125.796 116.75,125.796 117.429,125.117 119.41,125.117 124.166,120.361 124.166,118.964 124.624,118.507 127.912,118.507 141.663,104.755 147.595,104.755 152.487,99.863 v1(152.487,99.253) 152.487,86.863 149.454,83.83 148.057,83.83 139.26,75.033 139.26,62.327 133.437,56.505 133.437,50.187 132.5,49.25 P8.78@132.5,49 132.5,47.638 133.437,46.701 133.437,45.187 132.348,44.098 132.348,43.271 126.785,37.709 125.233,37.709 v1(125.206,37.682)
SD14: P3.16 P7.50 P8.79 P9.79 R59.1 U1.12 UN1.88 | length 302.3
  Top Layer w0.203: UN1.88@28.301,37.775 28.301,34.439 32.904,29.835 42.967,29.835 52.273,39.141 53.467,39.141 55.855,41.529 58.183,41.529 58.317,41.395 61.483,41.395 61.582,41.494 119.82,41.494 122.97,38.344 v1(123.023,38.344) ; P7.50@95.3,131.2 95.3,130.95 96.353,129.897 96.353,128.565 97.598,127.32 106.259,127.32 107.783,128.844 111.495,128.844 114.21,126.129 v1(114.21,124.78) ; v1(150.76,98.491) 152.081,99.812 164.376,99.812 166.931,102.367 168.856,102.367 170.305,103.816 U1.12@170.305,104.994
  Bottom Layer w0.203: v1(56.82,41.554) 56.82,26.06 58.68,24.2 P3.16@58.9,24.2 ; P7.50@95.3,131.2 95.3,130.95 96.105,130.145 96.105,128.113 95.558,127.567 R59.1@95.558,125.7 ; v1(114.21,124.78) 114.21,124.727 114.74,124.196 116.216,124.196 116.648,123.764 118.655,123.764 122.693,119.726 122.693,115.179 123.303,114.57 129.761,114.57 143.833,100.498 148.754,100.498 v1(150.76,98.491) ; v1(123.023,38.344) 124.09,39.411 126.275,39.411 129.602,42.738 129.602,44.852 130.5,45.75 P9.79@130.5,46 ; P9.79@130.384,46.116 130.384,46.865 129.558,47.691 129.558,49.622 P8.79@130.5,50.564 ; P8.79@130.5,51 130.5,55.854 137.719,63.072 137.719,75.671 147.419,85.371 149.146,85.371 150.786,87.011 v1@150.786,98.491
SD15: P3.18 P7.52 P8.80 P9.80 R60.1 U1.13 UN1.87 | length 299
  Top Layer w0.203: UN1.87@27.651,37.775 27.651,34.17 32.62,29.2 43.119,29.2 52.476,38.557 53.594,38.557 56.032,40.996 57.369,40.996 57.379,41.005 119.398,41.005 122.617,37.785 123.255,37.785 123.278,37.809 v1(123.493,37.809) ; P7.52@97.3,131.2 97.3,130.95 98.335,129.915 98.335,128.463 98.97,127.828 106.107,127.828 107.555,129.276 111.771,129.276 114.946,126.101 v1(114.946,124.78) ; v1(150.938,99.558) 151.725,100.346 164.197,100.346 166.722,102.871 168.653,102.871 169.797,104.015 169.797,104.986 U1.13@169.805,104.994
  Bottom Layer w0.203: v1(57.379,40.97) 57.379,27.457 58.636,26.2 P3.18@58.9,26.2 ; R60.1@97.2,125.7 97.2,127.024 98.114,127.938 98.114,130.136 97.3,130.95 P7.52@97.3,131.2 ; v1(114.946,124.78) 116.432,124.78 116.927,124.285 118.87,124.285 123.125,120.031 123.125,117.237 123.947,116.414 128.599,116.414 131.157,113.856 144.033,100.981 149.516,100.981 v1(150.938,99.558) 151.37,99.126 151.37,86.96 149.267,84.857 147.631,84.857 138.232,75.458 138.232,62.85 131.405,56.023 131.405,50.155 130.5,49.25 P8.80@130.5,49 130.5,47.638 131.437,46.701 131.437,45.361 130.5,44.424 P9.80@130.5,44 130.5,42.925 126.452,38.878 124.268,38.878 123.913,38.523 123.913,38.229 v1(123.493,37.809)
SMEMR#: P5.23 P8.10 P9.10 R32.1 U1.168 U10.24 UN1.31 | length 322.2
  Top Layer w0.203: UN1.31@36.101,62.475 36.101,63.994 37.451,65.344 46.363,65.344 v1(46.389,65.37) ; v1@46.403,65.356 46.417,65.37 v1(87.489,65.37) 110.043,65.37 117.866,57.547 194.774,57.547 195.079,57.851 v1(195.693,57.851) ; U1.168@178.463,82.336 184.973,82.336 185.431,82.794 191.146,82.794 v1(191.553,83.201)
  Bottom Layer w0.203: v1(46.389,65.37) 36.232,75.528 36.232,85.41 36.867,86.045 36.867,87.16 37.451,87.744 37.451,88.789 39.07,90.408 39.07,109.824 49.44,120.194 49.44,127.447 50.114,128.122 50.114,130.603 50.17,130.659 P5.23@50.17,133.9 50.17,134.2 49.196,135.174 R32.1@49.196,138.7 ; U10.24@85.838,50.612 86.793,51.567 86.793,53.899 86.574,54.118 86.574,55.079 86.793,55.297 86.793,57.13 87.413,57.75 87.413,65.098 87.43,65.116 87.43,65.311 v1(87.489,65.37) ; v1(191.553,83.201) v1@191.578,83.226 ; v1@191.578,83.201 191.578,61.992 201.549,52.021 201.549,50.299 200.5,49.25 P8.10@200.5,49 200.5,47.638 201.437,46.701 201.437,45.187 P9.10@200.5,44.25
SMEMW#: P5.21 P8.9 P9.9 R31.1 U1.170 UN1.32 | length 301.4
  Top Layer w0.203: UN1.32@35.451,62.475 35.451,64.208 37.171,65.929 v1(45.023,65.929) 110.116,65.929 117.939,58.105 v1(194.448,58.105) ; U1.170@178.463,83.336 190.589,83.336 190.937,83.683 v1(191.019,83.683)
  Bottom Layer w0.203: v1(45.023,65.929) 45.023,65.982 35.749,75.256 35.749,86.297 35.724,86.322 35.724,104.232 36.486,104.994 36.486,110.887 43.902,118.303 43.902,129.872 47.63,133.6 P5.21@47.63,133.9 47.63,134.2 46.484,135.346 46.484,138.357 R31.1@46.141,138.7 ; v1@191.022,83.683 190.994,83.655 190.994,81.908 191.019,81.883 191.019,61.56 194.448,58.131 v1(194.448,58.105) ; v1@194.461,58.118 200.5,52.079 P8.9@200.5,51 ; P9.9@200.384,46.116 200.384,46.865 199.558,47.691 199.558,49.622 P8.9@200.5,50.564
SPKR: R4.1 U1.32 | length 224.9
  Top Layer w0.203: v1(19.595,9.007) 56.982,9.007 57.76,8.23 87.732,8.23 v1(87.757,8.255) ; v1(87.757,21.768) 105.486,21.768 107.62,23.901 v1(121.488,23.901) ; v1(150.176,91.379) 150.189,91.367 161.161,91.367 v1(161.174,91.354) ; U1.32@160.305,104.994 160.305,103.4 v1(161.149,102.555)
  Bottom Layer w0.203: R4.1@17,9.6 19.002,9.6 v1(19.595,9.007) ; v1(87.757,8.255) v1(87.757,21.768) ; v1(121.488,23.901) 121.488,43.565 129.932,52.009 129.932,56.023 137.247,63.338 137.247,75.987 147.103,85.842 148.982,85.842 150.201,87.061 v1@150.201,91.379 ; v1(161.149,102.555) 161.161,102.543 161.161,91.367 v1(161.174,91.354)
STEP#: P7.10 U12.8 | length 54.8
  Top Layer w0.203: U12.8@39.026,91.129 41.03,91.129 42.153,90.006 42.607,89.552 42.607,88.433 v1(42.658,88.382)
  Bottom Layer w0.203: v1(42.658,88.382) 42.658,88.465 42.988,88.795 42.988,90.44 42.582,90.846 42.582,91.377 43.27,92.065 43.27,105.875 56.422,119.027 56.422,126.739 56.094,127.066 56.094,128.006 56.105,128.017 56.105,130.145 55.3,130.95 P7.10@55.3,131.2
TC: P5.53 P8.41 P9.41 R24.2 U1.14 U12.35 | length 264.8
  Top Layer w0.203: U12.35@33.501,108.354 33.501,109.964 47.987,124.45 66,124.45 66.153,124.298 v1(76.033,124.298) 76.116,124.298 76.294,124.476 82.188,124.476 86.27,128.558 86.27,131.6 88.27,133.6 P5.53@88.27,133.9 ; U1.14@169.305,104.994 169.323,105.012 169.323,106.183 170.369,107.229 v1(172.68,107.229)
  Layer 2 w0.203: v1(76.033,124.298) 78.134,124.298 79.81,122.621 80.097,122.621 81.901,120.818 82.757,120.818 83.679,119.897 83.679,119.802 84.161,119.319 86.32,119.319 87.809,117.831 89.2,117.831 89.876,118.507 93.709,118.507 94.877,117.338 98.028,117.338 102.473,112.893 113.117,112.893 115.835,110.175 121.296,110.175 122.947,108.524 132.929,108.524 142.327,117.922 142.632,117.922 143.343,118.634 143.343,120.335 144.817,121.809 167.651,121.809 v1(169.531,119.929)
  Bottom Layer w0.203: R24.2@87.353,138.7 87.353,135.117 88.27,134.2 P5.53@88.27,133.9 ; P9.41@168.384,46.116 168.384,46.865 167.558,47.691 167.558,49.622 P8.41@168.5,50.564 ; P8.41@168.5,51 168.5,52.782 174.052,58.334 174.052,67.512 174.019,67.545 174.019,72.667 173.95,72.736 173.95,76.622 173.595,76.978 173.595,102.965 172.68,103.879 v1(172.68,107.229) 172.706,107.254 172.706,116.779 v1@169.543,119.942
TEST#: R85.1 U1.2 | length 3.6
  Top Layer w0.203: U1.2@175.305,104.994 175.305,103.224 v1(175.329,103.2)
  Bottom Layer w0.203: R85.1@174.4,104.6 174.743,104.257 174.743,103.719 175.262,103.2 v1(175.329,103.2)
TFT_CS#: P4.11 R16.1 | length 7
  Top Layer w0.203: R16.1@120.999,125.362 121.337,125.024 121.612,125.024 122.221,124.414 126.236,124.414 127.05,123.6 P4.11@127.3,123.6
TFT_DC: P4.10 R11.1 | length 5.3
  Top Layer w0.203: R11.1@120.999,123.974 122.676,123.974 125.05,121.6 P4.10@125.3,121.6
TFT_RST: P4.3 R12.1 | length 6.9
  Top Layer w0.203: R12.1@120.999,114.262 121.306,114.57 126.02,114.57 127.05,115.6 P4.3@127.3,115.6
TFT_SCK: P4.7 R14.1 | length 7.2
  Top Layer w0.203: R14.1@120.999,119.812 122.099,119.812 123.303,118.608 126.058,118.608 127.05,119.6 P4.7@127.3,119.6
TFT_SDA: P4.6 R9.1 | length 4.6
  Top Layer w0.203: R9.1@120.999,118.424 122.09,118.424 122.914,117.6 P4.6@125.3,117.6
TFT_SW: P4.1 U2.41 | length 113.3
  Top Layer w0.203: U2.41@115.256,18.928 115.275,18.946 115.275,19.764 116.109,20.599 118.999,20.599 v1(119.634,21.234) ; P4.1@127.3,113.6 127.549,113.6 128.383,112.766 v1(130.389,112.766)
  Bottom Layer w0.203: v1(119.634,21.234) 119.634,24.359 120.356,25.081 120.356,43.916 128.27,51.829 128.27,57.45 132.155,61.335 132.155,70.995 129.767,73.382 129.767,76.681 137.755,84.669 137.755,99.99 130.389,107.356 v1(130.389,112.766)
TPIN+: J2.5 RN4.2 UN1.59 | length 56.9
  Top Layer w0.203: UN1.59@20.826,54.35 23.916,54.35 v1(24.359,54.792)
  Bottom Layer w0.203: v1(24.359,54.792) 24.935,54.215 24.935,24.52 34.05,15.406 34.05,10.504 33.646,10.1 RN4.2@32.8,10.1 32.854,10.046 J2.5@32.854,6.696
TPIN-: J2.7 RN3.2 UN1.58 | length 56.4
  Top Layer w0.203: UN1.58@20.826,55 23.437,55 v1(23.481,54.956)
  Bottom Layer w0.203: v1(23.481,54.956) 23.481,54.88 24.522,53.838 24.522,24.349 30.466,18.405 30.466,16.14 27.28,12.954 27.28,10.465 27.589,10.156 28.544,10.156 28.854,9.846 J2.7@28.854,6.696
TPOUT+: CN3.1 J2.1 UN1.45 | length 62.3
  Top Layer w0.203: v1(26.961,61.026) 26.981,61.046 26.981,62.455 UN1.45@27.001,62.475
  Bottom Layer w0.203: v1(26.961,61.026) 26.961,59.985 26.58,59.604 26.58,25.249 39.356,12.473 39.356,10.785 39.788,10.353 40.547,10.353 CN3.1@40.8,10.1 40.854,10.046 J2.1@40.854,6.696
TPOUT-: CN4.1 J2.3 UN1.46 | length 62.9
  Top Layer w0.203: UN1.46@26.351,62.475 26.363,62.462 26.363,60.633 v1(26.376,60.62)
  Bottom Layer w0.203: v1(26.376,60.62) 26.376,60.01 26.122,59.756 26.122,25.06 38.899,12.284 38.899,10.76 38.518,10.379 37.079,10.379 CN4.1@36.8,10.1 36.854,10.046 J2.3@36.854,6.696
TR0#: P7.14 R141.1 U12.13 | length 59
  Top Layer w0.203: U12.13@39.026,94.379 41.081,94.379 42.277,93.183 42.277,91.922 44.26,89.939 44.603,89.597 R141.1@44.641,89.597 44.679,89.597 45.464,88.812 45.464,88.71 v1(45.522,88.652)
  Bottom Layer w0.203: v1(45.522,88.652) 45.533,88.662 45.533,90.144 46.803,91.414 46.803,93.174 46.333,93.644 46.333,104.606 59.485,117.758 59.485,127.816 60.105,128.435 60.105,130.145 59.3,130.95 P7.14@59.3,131.2
TXD1: U12.79 U13.6 | length 155.8
  Top Layer w0.203: U12.79@20.826,87.229 22.501,87.229 v1(22.897,86.833) ; U13.6@144.2,123.1 145.989,123.1 147.636,121.453 147.636,116.805 v1(147.687,116.754)
  Layer 2 w0.203: v1(22.897,86.833) 23.481,86.249 23.481,82.185 24.802,80.864 25.982,80.864 27.199,82.081 48.418,82.081 61.576,95.24 62.669,95.24 69.349,101.92 132.842,101.92 145.846,114.925 146.239,114.925 147.685,116.372 147.685,116.753 v1(147.687,116.754)
USBCS#: U9.27 U18.4 | length 47.4
  Top Layer w0.203: U9.27@31.2,25.63 31.832,25.63 34.163,23.299 v1(34.163,22.911) ; v1(39.675,18.694) 54.915,18.694 58.223,15.386 65.551,15.386 65.595,15.342 U18.4@74.128,15.342
  Bottom Layer w0.203: v1(34.163,22.911) 34.163,22.909 38.378,18.694 v1(39.675,18.694)
VBAT: BAT2.3 BAT2.4 C80.1 Q5.5 Q5.6 Q5.7 Q5.8 R96.1 RP3.2 UP1.3 | length 2.6
  Top Layer w0.508: R96.1@203.662,10.406 203.715,10.353 205.283,10.353 C80.1@205.359,10.43 205.37,10.419 v1(205.37,9.591)
  other v1: 239.789,15.022 240.399,15.022 241.009,15.022 239.789,15.632 240.399,15.632 241.009,15.632 206.462,17.618 207.072,17.618 206.462,18.227 207.072,18.227 206.462,18.837 207.072,18.837
VCC1: C24.1 C28.1 CP9.1 CP10.1 CP11.1 LP1.1 R110.2 RP1.2 RP2.2 UP7.5 UP7.8 | length 16.1
  Top Layer w0.305: UP7.8@195.794,89.982 195.794,91.329 198.173,93.707 198.173,97.949 198.487,98.263 199.731,98.263
  Top Layer w0.508: 206.945,103.444 207.021,103.368 R110.2@207.021,97.982
VCC_ISA: C33.2 C34.2 C35.2 C77.2 JP2.2 P5.5 P5.57 R150.1 UP5.1 | length 3.2
  Top Layer w0.508: v2(16.231,131.75) JP2.2@17.082,131.75
  Bottom Layer w0.508: UP5.1@15.932,134.017 15.932,132.048 v2(16.231,131.75)
VCC_USB: C78.2 JP1.2 R151.1 UP4.1 USB1.VCC | length 14.2
  Top Layer w0.508: v2(9.322,24.765) JP1.2@9.322,25.819
  Bottom Layer w0.508: USB1.VCC@9.2,19.54 9.32,19.42 13.28,19.42 C78.2@13.4,19.3 ; USB1.VCC@9.322,19.662 v2(9.322,24.765) ; R151.1@13.393,17.457 13.393,19.293 C78.2@13.4,19.3 ; UP4.1@13.437,21.123 13.421,21.123 13.4,21.102 C78.2@13.4,19.3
